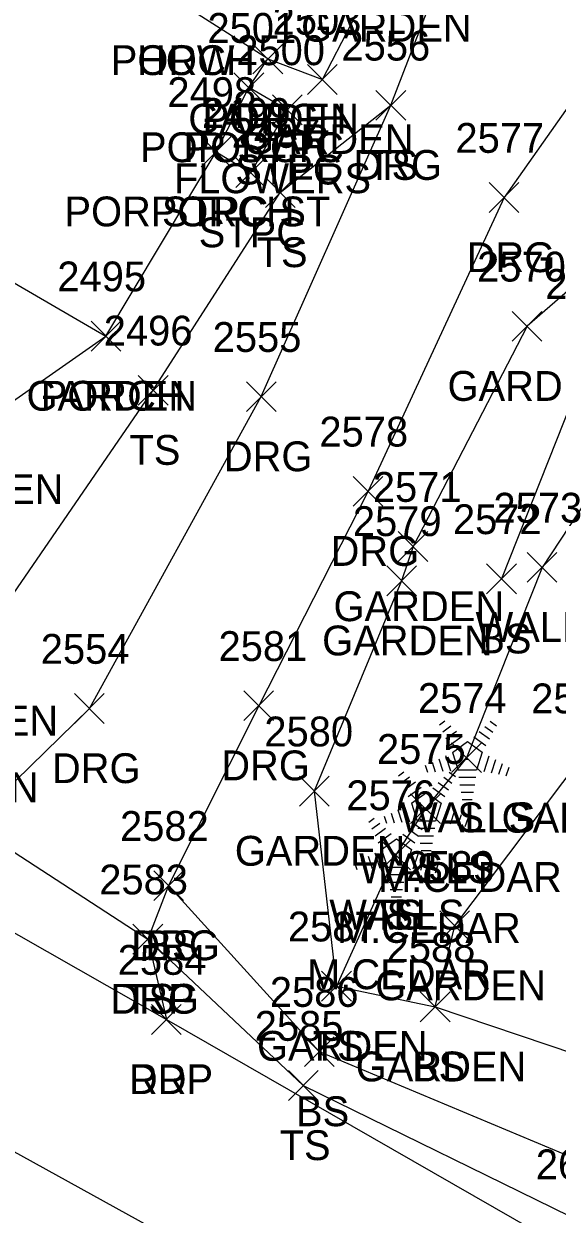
# Model space of a CAD drawing. Extents: x 1499292 to 1501024, y 534584 to 538043.
# Drawn here: x 1499556.7 to 1499592.5, y 537866.2 to 537946 of the extents above; entities that cross this region are included whole.
import ezdxf

# ---------------------------------------------------------------- set-up
doc = ezdxf.new("R2010")
doc.units = 0
for name, color, linetype in [('L_A', 7, 'Continuous'), ('L_C', 7, 'Continuous'), ('L_I', 7, 'Continuous'), ('L_TIC', 7, 'Continuous'), ('LAPB', 7, 'Continuous'), ('LBF', 7, 'Continuous'), ('LELB', 7, 'Continuous'), ('LTC', 7, 'Continuous'), ('LWS', 7, 'Continuous'), ('P_A', 7, 'Continuous'), ('P_I', 7, 'Continuous'), ('P_TIC', 7, 'Continuous'), ('PET', 7, 'Continuous'), ('PRC', 7, 'Continuous'), ('R_A', 7, 'Continuous'), ('R_I', 7, 'Continuous'), ('R_TIC', 7, 'Continuous'), ('RDG', 7, 'Continuous'), ('RDP', 7, 'Continuous')]:
    doc.layers.add(name, color=color, linetype=linetype)

msp = doc.modelspace()

# ---------------------------------------------------------------- linework, layer by layer
at = {"layer": 'L_TIC'}
for points in [[(1499572.098, 537942.68), (1499574.098, 537944.68)], [(1499574.098, 537942.68), (1499572.098, 537944.68)], [(1499572.098, 537942.68), (1499574.098, 537944.68)], [(1499574.098, 537942.68), (1499572.098, 537944.68)], [(1499570.824, 537940.761), (1499572.824, 537942.761)], [(1499572.824, 537940.761), (1499570.824, 537942.761)], [(1499570.824, 537940.761), (1499572.824, 537942.761)], [(1499572.824, 537940.761), (1499570.824, 537942.761)], [(1499575.761, 537941.303), (1499577.761, 537943.303)], [(1499577.761, 537941.303), (1499575.761, 537943.303)], [(1499573.406, 537939.265), (1499575.406, 537941.265)], [(1499575.406, 537939.265), (1499573.406, 537941.265)], [(1499580.355, 537939.574), (1499582.355, 537941.574)], [(1499582.355, 537939.574), (1499580.355, 537941.574)], [(1499568.625, 537936.456), (1499570.625, 537938.456)], [(1499570.625, 537936.456), (1499568.625, 537938.456)], [(1499568.625, 537936.456), (1499570.625, 537938.456)], [(1499570.625, 537936.456), (1499568.625, 537938.456)], [(1499570.95, 537935.055), (1499572.95, 537937.055)], [(1499572.95, 537935.055), (1499570.95, 537937.055)], [(1499572.937, 537933.723), (1499574.937, 537935.723)], [(1499574.937, 537933.723), (1499572.937, 537935.723)], [(1499589.485, 537924.756), (1499591.485, 537926.756)], [(1499591.485, 537924.756), (1499589.485, 537926.756)], [(1499561.242, 537924.098), (1499563.242, 537926.098)], [(1499563.242, 537924.098), (1499561.242, 537926.098)], [(1499561.242, 537924.098), (1499563.242, 537926.098)], [(1499563.242, 537924.098), (1499561.242, 537926.098)], [(1499561.242, 537924.098), (1499563.242, 537926.098)], [(1499563.242, 537924.098), (1499561.242, 537926.098)], [(1499564.41, 537920.467), (1499566.41, 537922.467)], [(1499566.41, 537920.467), (1499564.41, 537922.467)], [(1499581.838, 537909.985), (1499583.838, 537911.985)], [(1499583.838, 537909.985), (1499581.838, 537911.985)], [(1499590.493, 537908.589), (1499592.493, 537910.589)], [(1499592.493, 537908.589), (1499590.493, 537910.589)], [(1499581.072, 537907.689), (1499583.072, 537909.689)], [(1499583.072, 537907.689), (1499581.072, 537909.689)], [(1499587.775, 537907.82), (1499589.775, 537909.82)], [(1499589.775, 537907.82), (1499587.775, 537909.82)], [(1499585.43, 537895.83), (1499587.43, 537897.83)], [(1499587.43, 537895.83), (1499585.43, 537897.83)], [(1499575.215, 537893.586), (1499577.215, 537895.586)], [(1499577.215, 537893.586), (1499575.215, 537895.586)], [(1499582.679, 537892.415), (1499584.679, 537894.415)], [(1499584.679, 537892.415), (1499582.679, 537894.415)], [(1499580.68, 537889.308), (1499582.68, 537891.308)], [(1499582.68, 537889.308), (1499580.68, 537891.308)], [(1499580.68, 537889.308), (1499582.68, 537891.308)], [(1499582.68, 537889.308), (1499580.68, 537891.308)], [(1499565.448, 537887.249), (1499567.448, 537889.249)], [(1499567.448, 537887.249), (1499565.448, 537889.249)], [(1499584.633, 537884.562), (1499586.633, 537886.562)], [(1499586.633, 537884.562), (1499584.633, 537886.562)], [(1499564.054, 537883.662), (1499566.054, 537885.662)], [(1499566.054, 537883.662), (1499564.054, 537885.662)], [(1499576.703, 537880.508), (1499578.703, 537882.508)], [(1499578.703, 537880.508), (1499576.703, 537882.508)], [(1499576.703, 537880.508), (1499578.703, 537882.508)], [(1499578.703, 537880.508), (1499576.703, 537882.508)], [(1499583.328, 537879.125), (1499585.328, 537881.125)], [(1499585.328, 537879.125), (1499583.328, 537881.125)], [(1499583.328, 537879.125), (1499585.328, 537881.125)], [(1499585.328, 537879.125), (1499583.328, 537881.125)], [(1499575.549, 537876.121), (1499577.549, 537878.121)], [(1499577.549, 537876.121), (1499575.549, 537878.121)], [(1499574.48, 537873.847), (1499576.48, 537875.847)], [(1499576.48, 537873.847), (1499574.48, 537875.847)]]:
    msp.add_lwpolyline(points, dxfattribs=at)
at = {"layer": 'LAPB'}
for points in [[(1499573.098, 537943.68), (1499576.761, 537942.303), (1499580.662, 537949.841), (1499574.241, 537954.542), (1499576.151, 537959.257), (1499582.864, 537956.696)], [(1499606.629, 537948.337), (1499599.775, 537933.802), (1499590.485, 537925.756), (1499582.838, 537910.985), (1499582.072, 537908.689), (1499576.215, 537894.586), (1499577.703, 537881.508), (1499584.328, 537880.125), (1499585.633, 537885.562), (1499594.11, 537896.805), (1499602.213, 537917.838)], [(1499553.274, 537918.838), (1499562.242, 537925.098)]]:
    msp.add_lwpolyline(points, dxfattribs=at)
at = {"layer": 'LBF'}
for points in [[(1499538.424, 537947.137), (1499535.008, 537940.909), (1499562.242, 537925.098), (1499569.625, 537937.456), (1499571.824, 537941.761), (1499573.098, 537943.68), (1499566.943, 537947.6)], [(1499569.625, 537937.456), (1499571.95, 537936.055), (1499574.406, 537940.265), (1499571.824, 537941.761)]]:
    msp.add_lwpolyline(points, dxfattribs=at)
at = {"layer": 'LELB'}
for points in [[(1499510.207, 537921.367), (1499532.132, 537918.714), (1499542.324, 537919.18), (1499551.778, 537913.978), (1499552.919, 537903.309), (1499565.41, 537921.467), (1499573.937, 537934.723), (1499581.355, 537940.574)], [(1499599.775, 537933.802), (1499595.027, 537924.594), (1499588.775, 537908.82)], [(1499581.68, 537890.308), (1499577.703, 537881.508)], [(1499566.448, 537888.249), (1499576.549, 537877.121), (1499595.778, 537869.076), (1499609.124, 537863.443)], [(1499565.054, 537884.662), (1499575.48, 537874.847), (1499594.46, 537865.561), (1499606.958, 537860.671)], [(1499584.328, 537880.125), (1499599.362, 537875.044), (1499614.263, 537870.665)]]:
    msp.add_lwpolyline(points, dxfattribs=at)
at = {"layer": 'LTC'}
for p, q in [((1499584.625, 537899.039), (1499584.98, 537899.296)), ((1499584.835, 537898.573), (1499585.364, 537898.957)), ((1499587.652, 537898.931), (1499588.202, 537898.532)), ((1499588.024, 537899.279), (1499588.443, 537898.974)), ((1499585.044, 537898.107), (1499585.748, 537898.619)), ((1499585.254, 537897.642), (1499586.132, 537898.279)), ((1499586.91, 537898.234), (1499587.72, 537897.645)), ((1499587.282, 537898.582), (1499587.961, 537898.089)), ((1499585.479, 537897.187), (1499586.49, 537897.921)), ((1499586.49, 537897.921), (1499587.487, 537897.196)), ((1499584.113, 537896.534), (1499584.325, 537895.883)), ((1499584.569, 537896.751), (1499584.84, 537895.916)), ((1499585.024, 537896.967), (1499585.355, 537895.948)), ((1499585.479, 537897.187), (1499585.866, 537895.993)), ((1499587.487, 537897.196), (1499587.096, 537895.993)), ((1499587.925, 537896.925), (1499587.587, 537895.886)), ((1499588.369, 537896.675), (1499588.082, 537895.79)), ((1499588.814, 537896.425), (1499588.577, 537895.695)), ((1499581.875, 537895.623), (1499582.229, 537895.881)), ((1499583.658, 537896.318), (1499583.81, 537895.85)), ((1499585.273, 537895.863), (1499585.692, 537895.559)), ((1499587.096, 537895.993), (1499585.866, 537895.993)), ((1499589.258, 537896.174), (1499589.072, 537895.6)), ((1499582.084, 537895.158), (1499582.613, 537895.542)), ((1499582.294, 537894.692), (1499582.998, 537895.203)), ((1499582.503, 537894.226), (1499583.382, 537894.864)), ((1499584.16, 537894.818), (1499584.969, 537894.23)), ((1499584.531, 537895.167), (1499585.21, 537894.673)), ((1499584.902, 537895.515), (1499585.451, 537895.116)), ((1499587.058, 537895.493), (1499585.913, 537895.493)), ((1499586.974, 537894.993), (1499585.986, 537894.993)), ((1499582.728, 537893.771), (1499583.74, 537894.506)), ((1499583.74, 537894.506), (1499584.737, 537893.781)), ((1499586.89, 537894.493), (1499586.059, 537894.493)), ((1499581.818, 537893.336), (1499582.089, 537892.5)), ((1499582.273, 537893.552), (1499582.604, 537892.533)), ((1499582.728, 537893.771), (1499583.115, 537892.578)), ((1499584.737, 537893.781), (1499584.345, 537892.578)), ((1499585.174, 537893.51), (1499584.836, 537892.47)), ((1499585.619, 537893.259), (1499585.331, 537892.375)), ((1499586.807, 537893.993), (1499586.132, 537893.993)), ((1499579.875, 537892.517), (1499580.23, 537892.774)), ((1499580.085, 537892.051), (1499580.614, 537892.435)), ((1499580.907, 537892.902), (1499581.059, 537892.434)), ((1499581.363, 537893.119), (1499581.574, 537892.467)), ((1499584.345, 537892.578), (1499583.115, 537892.578)), ((1499583.274, 537892.757), (1499583.693, 537892.452)), ((1499586.063, 537893.009), (1499585.826, 537892.28)), ((1499586.508, 537892.759), (1499586.321, 537892.185)), ((1499580.294, 537891.585), (1499580.998, 537892.097)), ((1499580.504, 537891.12), (1499581.382, 537891.757)), ((1499582.16, 537891.712), (1499582.97, 537891.123)), ((1499582.531, 537892.06), (1499583.211, 537891.567)), ((1499582.902, 537892.409), (1499583.452, 537892.01)), ((1499584.307, 537892.078), (1499583.163, 537892.078)), ((1499580.729, 537890.665), (1499581.74, 537891.399)), ((1499581.74, 537891.399), (1499582.737, 537890.674)), ((1499584.223, 537891.578), (1499583.235, 537891.578)), ((1499584.14, 537891.078), (1499583.308, 537891.078)), ((1499579.819, 537890.229), (1499580.09, 537889.394)), ((1499580.274, 537890.445), (1499580.605, 537889.426)), ((1499580.729, 537890.665), (1499581.116, 537889.471)), ((1499582.737, 537890.674), (1499582.346, 537889.471)), ((1499583.175, 537890.403), (1499582.837, 537889.364)), ((1499583.619, 537890.153), (1499583.332, 537889.268)), ((1499584.056, 537890.578), (1499583.381, 537890.578)), ((1499578.908, 537889.796), (1499579.06, 537889.328)), ((1499579.363, 537890.012), (1499579.575, 537889.361)), ((1499582.346, 537889.471), (1499581.116, 537889.471)), ((1499584.064, 537889.903), (1499583.827, 537889.173)), ((1499584.508, 537889.652), (1499584.321, 537889.078)), ((1499582.308, 537888.971), (1499581.163, 537888.971)), ((1499582.224, 537888.471), (1499581.236, 537888.471)), ((1499582.14, 537887.971), (1499581.309, 537887.971)), ((1499582.056, 537887.471), (1499581.381, 537887.471))]:
    msp.add_line(p, q, dxfattribs=at)
at = {"layer": 'LWS'}
msp.add_lwpolyline([(1499599.915, 537922.334), (1499591.493, 537909.589), (1499586.43, 537896.83), (1499583.679, 537893.415), (1499581.68, 537890.308)], dxfattribs=at)
at = {"layer": 'P_TIC'}
for points in [[(1499565.293, 537878.272), (1499567.293, 537880.272)], [(1499567.293, 537878.272), (1499565.293, 537880.272)]]:
    msp.add_lwpolyline(points, dxfattribs=at)
at = {"layer": 'PET'}
msp.add_lwpolyline([(1499318.777, 538007.185), (1499356.077, 537991.329), (1499396.207, 537971.039), (1499437.012, 537950.167), (1499476.074, 537929.172), (1499509.306, 537910.677), (1499546.423, 537890.59), (1499566.293, 537879.272), (1499602.082, 537858.76), (1499615.195, 537851.418), (1499643.027, 537835.063), (1499676.234, 537815.623), (1499707.101, 537797.403), (1499725.198, 537785.865), (1499749.466, 537768.587), (1499768.247, 537754.161), (1499782.48, 537740.777), (1499805.279, 537716.472), (1499820.533, 537699.08)], dxfattribs=at)
at = {"layer": 'PRC'}
msp.add_lwpolyline([(1499314.647, 537995.238), (1499351.896, 537980.059), (1499390.853, 537960.785), (1499432.771, 537938.063), (1499470.255, 537918.917), (1499503.529, 537899.736), (1499550.301, 537873.589), (1499594.281, 537849.334), (1499631.071, 537828.01), (1499665.93, 537807.267), (1499699.614, 537786.782), (1499728.317, 537767.815), (1499774.937, 537731.181), (1499796.918, 537710.716), (1499813.912, 537693.068)], dxfattribs=at)
at = {"layer": 'R_TIC'}
for points in [[(1499580.355, 537939.574), (1499582.355, 537941.574)], [(1499582.355, 537939.574), (1499580.355, 537941.574)], [(1499587.944, 537933.387), (1499589.944, 537935.387)], [(1499589.944, 537933.387), (1499587.944, 537935.387)], [(1499571.66, 537920.037), (1499573.66, 537922.037)], [(1499573.66, 537920.037), (1499571.66, 537922.037)], [(1499578.82, 537913.693), (1499580.82, 537915.693)], [(1499580.82, 537913.693), (1499578.82, 537915.693)], [(1499571.487, 537899.312), (1499573.487, 537901.312)], [(1499573.487, 537899.312), (1499571.487, 537901.312)], [(1499560.128, 537899.126), (1499562.128, 537901.126)], [(1499562.128, 537899.126), (1499560.128, 537901.126)], [(1499565.448, 537887.249), (1499567.448, 537889.249)], [(1499567.448, 537887.249), (1499565.448, 537889.249)], [(1499564.054, 537883.662), (1499566.054, 537885.662)], [(1499566.054, 537883.662), (1499564.054, 537885.662)], [(1499564.054, 537883.662), (1499566.054, 537885.662)], [(1499566.054, 537883.662), (1499564.054, 537885.662)], [(1499565.293, 537878.272), (1499567.293, 537880.272)], [(1499567.293, 537878.272), (1499565.293, 537880.272)]]:
    msp.add_lwpolyline(points, dxfattribs=at)
at = {"layer": 'RDG'}
for points in [[(1499553.185, 537892.375), (1499561.128, 537900.126), (1499572.66, 537921.037), (1499581.355, 537940.574), (1499588.537, 537959.177)], [(1499601.461, 537952.146), (1499588.944, 537934.387), (1499579.82, 537914.693), (1499572.487, 537900.312), (1499566.448, 537888.249), (1499565.054, 537884.662)]]:
    msp.add_lwpolyline(points, dxfattribs=at)
at = {"layer": 'RDP'}
msp.add_lwpolyline([(1499546.423, 537890.59), (1499548.752, 537890.981), (1499553.185, 537892.375), (1499565.054, 537884.662), (1499566.293, 537879.272)], dxfattribs=at)

# ---------------------------------------------------------------- texts
at = {"layer": 'L_A'}
for s, p in [('GARDEN', (1499575.331, 537944.841)), ('PORCH', (1499562.565, 537942.6)), ('HOW', (1499564.329, 537942.6)), ('GARDEN', (1499567.767, 537938.68)), ('PORCH', (1499568.72, 537938.68)), ('POR STPC', (1499564.525, 537936.761)), ('PORCH', (1499567.446, 537936.761)), ('GARDEN', (1499571.43, 537937.303)), ('STPC', (1499570.918, 537935.265)), ('TS', (1499579.765, 537935.574)), ('POR STPC ST', (1499559.459, 537932.456)), ('PORCH', (1499565.247, 537932.456)), ('STPC', (1499568.462, 537931.055)), ('TS', (1499572.347, 537929.723)), ('GARDEN', (1499585.154, 537920.756)), ('GARDEN', (1499556.911, 537920.098)), ('GARDEN', (1499556.911, 537920.098)), ('PORCH', (1499557.864, 537920.098)), ('TS', (1499563.819, 537916.467)), ('GARDEN', (1499547.944, 537913.838)), ('GARDEN', (1499547.944, 537913.838)), ('GARDEN', (1499577.507, 537905.985)), ('WALLS', (1499587.036, 537904.589)), ('GARDEN', (1499576.742, 537903.689)), ('BS', (1499587.216, 537903.82)), ('GARDEN', (1499547.589, 537898.309)), ('GARDEN', (1499546.272, 537893.843)), ('GARDEN', (1499546.272, 537893.843)), ('WALLS', (1499581.973, 537891.83)), ('S', (1499585.816, 537891.83)), ('GARDEN', (1499588.779, 537891.805)), ('GARDEN', (1499570.884, 537889.586)), ('WALLS', (1499579.223, 537888.415)), ('S', (1499583.065, 537888.415)), ('WALLS', (1499577.223, 537885.308)), ('TS', (1499580.089, 537885.308)), ('S', (1499581.066, 537885.308)), ('BS', (1499564.889, 537883.249)), ('GARDEN', (1499580.302, 537880.562)), ('TS', (1499563.463, 537879.662)), ('GARDEN', (1499572.373, 537876.508)), ('TS', (1499576.113, 537876.508)), ('GARDEN', (1499578.997, 537875.125)), ('BS', (1499582.769, 537875.125)), ('BS', (1499574.99, 537872.121)), ('TS', (1499573.89, 537869.847))]:
    msp.add_text(s, height=2, dxfattribs=at).set_placement(p)
at = {"layer": 'L_C'}
for s, p in [('FLOWERS', (1499566.799, 537934.68)), ('M.CEDAR', (1499580.485, 537887.83)), ('M.CEDAR', (1499577.735, 537884.415)), ('M.CEDAR', (1499575.735, 537881.308))]:
    msp.add_text(s, height=2, dxfattribs=at).set_placement(p)
at = {"layer": 'L_I'}
for s, p in [('2501', (1499569.052, 537944.761)), ('2501', (1499569.052, 537944.761)), ('2503', (1499573.422, 537945.303)), ('2500', (1499570.981, 537943.265)), ('2556', (1499578.04, 537943.574)), ('2498', (1499566.365, 537940.456)), ('2498', (1499566.365, 537940.456)), ('2499', (1499568.682, 537939.055)), ('2497', (1499570.678, 537937.723)), ('2570', (1499587.138, 537928.756)), ('2495', (1499558.982, 537928.098)), ('2495', (1499558.982, 537928.098)), ('2495', (1499558.982, 537928.098)), ('2569', (1499591.712, 537927.594)), ('2496', (1499562.095, 537924.467)), ('2571', (1499580.145, 537913.985)), ('2573', (1499588.233, 537912.589)), ('2579', (1499578.805, 537911.689)), ('2572', (1499585.515, 537911.82)), ('2574', (1499583.17, 537899.83)), ('2574', (1499583.17, 537899.83)), ('2590', (1499590.764, 537899.805)), ('2590', (1499590.764, 537899.805)), ('2580', (1499572.868, 537897.586)), ('2575', (1499580.42, 537896.415)), ('2575', (1499580.42, 537896.415)), ('2576', (1499578.365, 537893.308)), ('2576', (1499578.365, 537893.308)), ('2576', (1499578.365, 537893.308)), ('2582', (1499563.188, 537891.249)), ('2589', (1499582.365, 537888.562)), ('2583', (1499561.794, 537887.662)), ('2587', (1499574.443, 537884.508)), ('2587', (1499574.443, 537884.508)), ('2588', (1499581.068, 537883.125)), ('2588', (1499581.068, 537883.125)), ('2586', (1499573.234, 537880.121)), ('2585', (1499572.221, 537877.847)), ('2608', (1499591.074, 537868.561))]:
    msp.add_text(s, height=2, dxfattribs=at).set_placement(p)
at = {"layer": 'LTC'}
for p in [(1499586.373, 537896.934), (1499583.622, 537893.519), (1499581.623, 537890.412)]:
    msp.add_text('.', height=1.037, rotation=270, dxfattribs=at).set_placement(p)
at = {"layer": 'P_A'}
msp.add_text('RDP', height=2, dxfattribs=at).set_placement((1499563.781, 537874.272))
at = {"layer": 'P_I'}
msp.add_text('2584', height=2, dxfattribs=at).set_placement((1499563.033, 537882.272))
at = {"layer": 'R_A'}
for s, p in [('DRG', (1499578.844, 537935.574)), ('DRG', (1499586.433, 537929.387)), ('DRG', (1499570.148, 537916.037)), ('DRG', (1499577.308, 537909.693)), ('DRG', (1499569.975, 537895.312)), ('DRG', (1499558.616, 537895.126)), ('DRG', (1499563.936, 537883.249)), ('DRG', (1499562.542, 537879.662)), ('DRP', (1499562.542, 537879.662)), ('DRP', (1499563.781, 537874.272))]:
    msp.add_text(s, height=2, dxfattribs=at).set_placement(p)
at = {"layer": 'R_I'}
for s, p in [('2556', (1499578.04, 537943.574)), ('2577', (1499585.685, 537937.387)), ('2555', (1499569.4, 537924.037)), ('2578', (1499576.56, 537917.693)), ('2581', (1499569.794, 537903.312)), ('2554', (1499557.868, 537903.126)), ('2582', (1499563.188, 537891.249)), ('2583', (1499561.794, 537887.662)), ('2583', (1499561.794, 537887.662)), ('2584', (1499563.033, 537882.272))]:
    msp.add_text(s, height=2, dxfattribs=at).set_placement(p)

doc.saveas('drawing.dxf')
